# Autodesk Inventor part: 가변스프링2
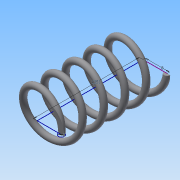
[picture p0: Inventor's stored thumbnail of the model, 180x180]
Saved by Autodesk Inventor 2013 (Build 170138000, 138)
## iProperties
Created: 2018-10
Part Number: 가변스프링2
Material: 일반
Document SubType Name: Modeling
Designer: Administrator
Density: 1 g/cm^3
Author: Administrator
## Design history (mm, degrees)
sketch "스케치1"
  geometry: L1 (0, 0)-(-8, 0); L2 (-8, 0)-(-8, 30.465); L3 (-8, 30.465)-(0, 30.465); C1 r 1 at (0, 0); 1 further point
  constraints: 6 end point, 1 centre point, 1 coincident, 1 horizontal, 1 parallel, 1 perpendicular, 1 vertical alignment
  dimensions: "d0" = 2 diameter of C1; "d2" = 30.46484 distance of L1.end L2.end (derived); "d3" = 8 distance of L2.end L3.end
feature "코일1" pitch "d4" = 10; turns "d6" = 5; dims "d5" = 30.46484 (= d2), "d7" = 0, angle "d8" = 90 deg, angle "d9" = 90 deg, "d10" = 0, "d11" = 0
sketch "스케치2"
  geometry: C1 r 22.863 at (0, 0); 1 further point
  constraints: 1 centre point, 1 coincident
extrude "돌출1" cut sketch "스케치2" distance "d12" = 10; taper "d13" = 0 deg
node "작업 평면1"
sketch "스케치3"
  geometry: C1 r 28.077 at (-8, 0); 1 further point
  constraints: 1 centre point, 1 coincident
extrude "돌출2" cut sketch "스케치3" distance "d14" = 10; taper "d15" = 0 deg
node "솔리드1"
